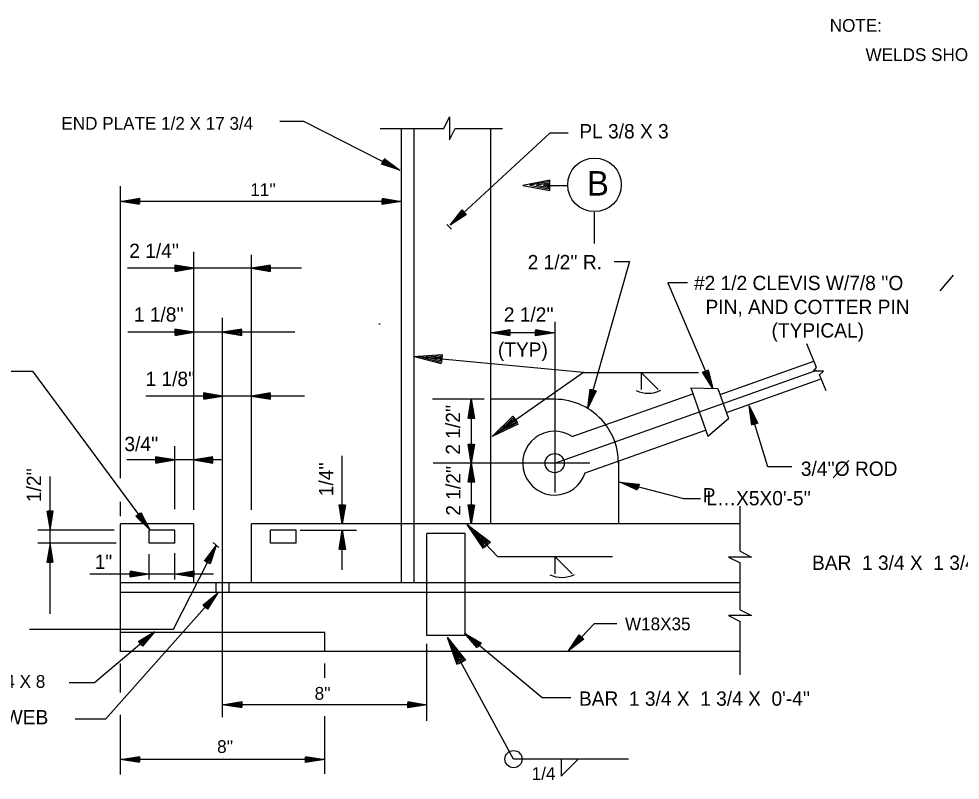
# Model space of a CAD drawing. Extents: x 0 to 13.3, y 0 to 9.3.
# Drawn here: x 2.16 to 5.231, y 1.508 to 3.991 of the extents above; entities that cross this region are included whole.
import ezdxf

# ---------------------------------------------------------------- set-up
doc = ezdxf.new("R2010")
doc.units = 0
for name, color, linetype in [('Level 13', 7, 'Continuous'), ('Level 2', 7, 'Continuous'), ('Level 25', 7, 'Continuous'), ('Level 3', 7, 'Continuous'), ('Level 44', 7, 'Continuous'), ('Level 50', 7, 'Continuous'), ('Level 7', 7, 'Continuous')]:
    doc.layers.add(name, color=color, linetype=linetype)

msp = doc.modelspace()

# ---------------------------------------------------------------- linework, layer by layer
at = {"layer": 'Level 13'}
for points in [[(3.5462, 3.6338), (3.5649, 3.6713), (3.5649, 3.5964), (3.5836, 3.6338)], [(4.5132, 2.2542), (4.5507, 2.2356), (4.4758, 2.2356), (4.5132, 2.2168)], [(4.5132, 2.0631), (4.5507, 2.0444), (4.4758, 2.0444), (4.5132, 2.0257)]]:
    msp.add_lwpolyline(points, dxfattribs=at)
at = {"layer": 'Level 2'}
for p, q in [((3.4081, 2.3437), (3.4081, 3.6338)), ((3.4497, 2.3437), (3.4497, 3.6338)), ((3.6997, 2.3437), (3.6997, 3.6338)), ((3.9082, 3.0024), (3.9082, 2.4464)), ((4.7627, 2.8541), (4.7304, 2.9316)), ((4.4478, 2.7663), (4.7536, 2.8746)), ((3.9082, 2.5419), (4.764, 2.8452)), ((4.7527, 2.8419), (4.7627, 2.8541)), ((4.7848, 2.8419), (4.7527, 2.8419)), ((4.7727, 2.8299), (4.7848, 2.8419)), ((4.7944, 2.7778), (4.7727, 2.8299)), ((4.4687, 2.7074), (4.7745, 2.8157)), ((3.9658, 2.6287), (4.3588, 2.7679)), ((4.3519, 2.7876), (4.4075, 2.6304)), ((4.3519, 2.7876), (4.4409, 2.7859)), ((4.4409, 2.7859), (4.4757, 2.6877)), ((3.9082, 2.7503), (3.6997, 2.7503)), ((4.4075, 2.6304), (4.4757, 2.6877)), ((4.0076, 2.5108), (4.4006, 2.65)), ((4.1166, 2.5494), (4.1166, 2.3437)), ((4.0226, 2.5419), (3.5122, 2.5419)), ((4.1166, 2.5419), (4.1166, 2.5377)), ((4.5132, 2.2542), (4.5132, 2.4014)), ((2.7311, 2.3437), (2.4914, 2.3437)), ((2.4914, 1.9271), (2.4914, 2.3437)), ((2.7311, 2.151), (2.7311, 2.3437)), ((2.9187, 2.151), (2.9187, 2.3437)), ((4.5132, 2.3437), (2.9187, 2.3437)), ((3.4081, 2.151), (3.4081, 2.3437)), ((3.4497, 2.151), (3.4497, 2.3437)), ((2.6685, 2.3229), (2.5852, 2.3229)), ((2.5852, 2.2812), (2.5852, 2.3229)), ((2.6685, 2.2812), (2.6685, 2.3229)), ((2.9812, 2.2812), (2.9812, 2.3229)), ((3.0646, 2.3229), (2.9812, 2.3229)), ((3.0646, 2.2812), (3.0646, 2.3229)), ((3.4914, 1.9791), (3.4914, 2.3125)), ((3.6164, 2.3125), (3.4914, 2.3125)), ((3.6164, 1.9791), (3.6164, 2.3125)), ((2.6685, 2.2812), (2.5852, 2.2812)), ((3.0646, 2.2812), (2.9812, 2.2812)), ((4.5132, 2.0631), (4.5132, 2.2168)), ((4.5132, 2.151), (2.4914, 2.151)), ((2.9187, 2.151), (2.7311, 2.151)), ((2.804, 2.1198), (2.804, 2.151)), ((2.8457, 2.1198), (2.8457, 2.151)), ((4.5132, 2.1198), (2.4914, 2.1198)), ((4.5132, 1.8511), (4.5132, 2.0257)), ((3.1581, 1.9896), (2.4914, 1.9896)), ((3.1581, 1.9271), (3.1581, 1.9896)), ((3.6164, 1.9791), (3.4914, 1.9791)), ((4.5132, 1.9271), (2.4914, 1.9271))]:
    msp.add_line(p, q, dxfattribs=at)
msp.add_circle((3.9081, 2.5419), 0.0313, dxfattribs=at)
for radius, start, end in [(0.2084, 39.3557, 90), (0.2084, 0, 39.3557), (0.1042, 56.3868, 342.6378)]:
    msp.add_arc((3.9081, 2.5419), radius, start, end, dxfattribs=at)
at = {"layer": 'Level 25'}
for p, q in [((4.0026, 2.8378), (3.4471, 2.8901)), ((3.4471, 2.8901), (3.4471, 2.8901)), ((3.4729, 2.8877), (3.4729, 2.8877)), ((4.0026, 2.8378), (4.3777, 2.8378)), ((4.1901, 2.8378), (4.1901, 2.7816)), ((4.1901, 2.8378), (4.246, 2.7819)), ((3.7254, 2.6432), (3.7254, 2.6432)), ((3.7041, 2.6283), (3.7041, 2.6283)), ((3.6232, 2.342), (3.6232, 2.342)), ((3.6409, 2.323), (3.6409, 2.323)), ((3.7213, 2.2371), (4.0964, 2.2371)), ((3.9088, 2.2371), (3.9088, 2.1809)), ((3.9088, 2.2371), (3.9648, 2.1812)), ((3.5587, 1.9735), (3.5587, 1.9735)), ((3.5711, 1.9507), (3.5711, 1.9507)), ((4.1491, 1.5763), (3.774, 1.5763)), ((3.9294, 1.5769), (3.9294, 1.5207)), ((3.9294, 1.5207), (3.9853, 1.5765))]:
    msp.add_line(p, q, dxfattribs=at)
for points in [[(3.5387, 2.8659), (3.4471, 2.8901), (3.5416, 2.8968), (3.5391, 2.8704), (3.4729, 2.8877), (3.5371, 2.8922), (3.5356, 2.8752), (3.4978, 2.8853), (3.5327, 2.8876), (3.532, 2.8806), (3.5237, 2.8829)], [(3.7895, 2.6693), (3.7041, 2.6283), (3.7717, 2.6947), (3.7869, 2.673), (3.7254, 2.6432), (3.7713, 2.6883), (3.7811, 2.6744), (3.7458, 2.6576), (3.7709, 2.6819), (3.7749, 2.6762), (3.7671, 2.6725)], [(3.6758, 2.2631), (3.6232, 2.342), (3.6984, 2.2843), (3.679, 2.2662), (3.6409, 2.323), (3.692, 2.2838), (3.6796, 2.2722), (3.658, 2.3048), (3.6856, 2.2833), (3.6805, 2.2785), (3.6758, 2.2858)], [(3.5896, 1.8839), (3.5587, 1.9735), (3.6169, 1.8987), (3.5936, 1.8861), (3.5711, 1.9507), (3.6106, 1.8999), (3.5956, 1.8918), (3.583, 1.9287), (3.6043, 1.901), (3.5981, 1.8976), (3.5954, 1.9058)]]:
    msp.add_lwpolyline(points, dxfattribs=at)
at = {"layer": 'Level 3'}
for p, q in [((3.3877, 3.5059), (3.3877, 3.5059)), ((3.4031, 3.4981), (3.4031, 3.4981)), ((2.4914, 2.4925), (2.4914, 3.445)), ((3.8922, 3.4481), (3.9505, 3.4481)), ((3.4081, 3.3957), (2.4914, 3.3957)), ((4.038, 3.2589), (4.038, 3.3608)), ((3.5671, 3.3187), (3.5671, 3.3187)), ((3.5799, 3.3304), (3.5799, 3.3304)), ((2.7311, 2.3891), (2.7311, 3.2307)), ((2.9187, 2.3891), (2.9187, 3.221)), ((2.7311, 3.1775), (2.515, 3.1775)), ((2.7137, 3.1775), (2.7137, 3.1775)), ((2.9187, 3.1775), (2.7311, 3.1775)), ((2.7311, 3.1775), (2.7311, 3.1775)), ((3.0826, 3.1775), (2.9187, 3.1775)), ((2.9187, 3.1775), (2.9187, 3.1775)), ((2.936, 3.1775), (2.936, 3.1775)), ((5.1656, 3.1045), (5.2094, 3.1553)), ((2.8249, 1.7128), (2.8249, 3.0163)), ((3.339, 2.9955), (3.3345, 2.9955)), ((2.7311, 2.969), (2.5156, 2.969)), ((2.7137, 2.969), (2.7137, 2.969)), ((2.8249, 2.969), (2.7311, 2.969)), ((2.7311, 2.969), (2.7311, 2.969)), ((3.0602, 2.969), (2.8249, 2.969)), ((2.8249, 2.969), (2.8249, 2.969)), ((2.8422, 2.969), (2.8422, 2.969)), ((3.9082, 2.9671), (3.6997, 2.9671)), ((4.4174, 2.8011), (4.4174, 2.8011)), ((4.4241, 2.7851), (4.4241, 2.7851)), ((2.8249, 2.7606), (2.5738, 2.7606)), ((2.8075, 2.7606), (2.8075, 2.7606)), ((2.9187, 2.7606), (2.8249, 2.7606)), ((2.8249, 2.7606), (2.8249, 2.7606)), ((3.0922, 2.7606), (2.9187, 2.7606)), ((2.9187, 2.7606), (2.9187, 2.7606)), ((2.936, 2.7606), (2.936, 2.7606)), ((3.6783, 2.7503), (3.5101, 2.7503)), ((3.6359, 2.7503), (3.6359, 2.5419)), ((4.0214, 2.7374), (4.0214, 2.7374)), ((4.0167, 2.7207), (4.0167, 2.7207)), ((4.5432, 2.7286), (4.5432, 2.7286)), ((4.5482, 2.712), (4.5482, 2.712)), ((2.6685, 2.3923), (2.6685, 2.5971)), ((2.6685, 2.5522), (2.5122, 2.5522)), ((2.6512, 2.5522), (2.6512, 2.5522)), ((2.7311, 2.5522), (2.6685, 2.5522)), ((2.6685, 2.5522), (2.6685, 2.5522)), ((2.8202, 2.5522), (2.7311, 2.5522)), ((2.7311, 2.5522), (2.7311, 2.5522)), ((2.7484, 2.5522), (2.7484, 2.5522)), ((3.2151, 2.3437), (3.2151, 2.5652)), ((4.8168, 2.4938), (4.8674, 2.5505)), ((3.6359, 2.5419), (3.6359, 2.3437)), ((2.2621, 2.3229), (2.2621, 2.4979)), ((4.1211, 2.4795), (4.1211, 2.4795)), ((4.1379, 2.4751), (4.1379, 2.4751)), ((2.4914, 2.3694), (2.4914, 2.4159)), ((2.2621, 2.3402), (2.2621, 2.3402)), ((2.5768, 2.3388), (2.5768, 2.3388)), ((2.4714, 2.3229), (2.2218, 2.3229)), ((2.2621, 2.2611), (2.2621, 2.3229)), ((2.2621, 2.3229), (2.2621, 2.3229)), ((2.5871, 2.3248), (2.5871, 2.3248)), ((3.2151, 2.1941), (3.2151, 2.3229)), ((2.4778, 2.2812), (2.2218, 2.2812)), ((2.2621, 2.0499), (2.2621, 2.2812)), ((2.2621, 2.2812), (2.2621, 2.2812)), ((2.8036, 2.2733), (2.8036, 2.2733)), ((2.2621, 2.2639), (2.2621, 2.2639)), ((2.5852, 2.1626), (2.5852, 2.2451)), ((2.6685, 2.1626), (2.6685, 2.2483)), ((2.7958, 2.2579), (2.7958, 2.2579)), ((2.5852, 2.18), (2.3912, 2.18)), ((2.6685, 2.18), (2.5852, 2.18)), ((2.7946, 2.18), (2.6685, 2.18)), ((2.4429, 1.7062), (2.809, 2.1184)), ((2.5908, 1.9813), (2.5908, 1.9813)), ((2.604, 1.9924), (2.604, 1.9924)), ((3.6145, 1.9871), (3.6145, 1.9871)), ((3.6278, 1.976), (3.6278, 1.976)), ((3.4914, 1.7016), (3.4914, 1.9529)), ((3.9654, 1.9417), (3.9654, 1.9417)), ((3.9536, 1.9291), (3.9536, 1.9291)), ((2.4914, 1.7936), (2.4914, 1.8878)), ((3.1581, 1.8418), (3.1581, 1.8878)), ((3.4914, 1.7535), (2.8249, 1.7535)), ((2.4914, 1.5259), (2.4914, 1.7213)), ((2.4429, 1.7062), (2.3437, 1.7062)), ((3.1581, 1.5284), (3.1581, 1.7164)), ((3.1581, 1.5751), (2.4914, 1.5751))]:
    msp.add_line(p, q, dxfattribs=at)
for points in [[(3.0117, 3.6578), (3.0882, 3.6578), (3.4031, 3.4981)], [(3.952, 3.6184), (3.8929, 3.6184), (3.5671, 3.3187)], [(3.3522, 3.5355), (3.4031, 3.4981), (3.3429, 3.517), (3.3508, 3.5328), (3.3877, 3.5059), (3.3467, 3.5188), (3.3519, 3.5289), (3.3728, 3.5134), (3.3506, 3.5206), (3.3527, 3.5247), (3.3573, 3.5213)], [(3.8922, 3.4604), (3.8922, 3.4648), (3.8047, 3.4481), (3.8922, 3.4318), (3.8922, 3.4604), (3.827, 3.4484), (3.888, 3.4368), (3.888, 3.4556), (3.849, 3.4484), (3.8839, 3.4419), (3.8839, 3.4506), (3.8714, 3.4484), (3.8797, 3.4468)], [(3.62, 3.3533), (3.5671, 3.3187), (3.606, 3.3685), (3.618, 3.3555), (3.5799, 3.3304), (3.6063, 3.3642), (3.614, 3.3559), (3.5921, 3.3417), (3.6066, 3.3599), (3.6097, 3.3565), (3.6049, 3.3534)], [(4.1024, 3.1993), (4.1521, 3.1993), (4.0167, 2.7207)], [(2.6687, 3.1671), (2.7311, 3.1775), (2.6687, 3.1878), (2.6687, 3.1701), (2.7137, 3.1775), (2.6714, 3.1845), (2.6714, 3.1731), (2.6971, 3.1775), (2.6741, 3.1811), (2.6741, 3.1765), (2.6797, 3.1775)], [(2.981, 3.1878), (2.9187, 3.1775), (2.981, 3.1671), (2.981, 3.1848), (2.936, 3.1775), (2.9784, 3.1705), (2.9784, 3.1818), (2.9527, 3.1775), (2.9757, 3.1738), (2.9757, 3.1785), (2.97, 3.1775)], [(4.3411, 3.1297), (4.2774, 3.1297), (4.4241, 2.7851)], [(2.6687, 2.9587), (2.7311, 2.969), (2.6687, 2.9794), (2.6687, 2.9617), (2.7137, 2.969), (2.6714, 2.976), (2.6714, 2.9647), (2.6971, 2.969), (2.6741, 2.9727), (2.6741, 2.968), (2.6797, 2.969)], [(2.8872, 2.9794), (2.8249, 2.969), (2.8872, 2.9587), (2.8872, 2.9764), (2.8422, 2.969), (2.8846, 2.962), (2.8846, 2.9734), (2.8589, 2.969), (2.8819, 2.9654), (2.8819, 2.97), (2.8762, 2.969)], [(1.9936, 2.8419), (2.2049, 2.8419), (2.5871, 2.3248)], [(4.4092, 2.8465), (4.4241, 2.7851), (4.3902, 2.8384), (4.4065, 2.8453), (4.4174, 2.8011), (4.3943, 2.8373), (4.4048, 2.8417), (4.4108, 2.8164), (4.3984, 2.8361), (4.4027, 2.8379), (4.404, 2.8323)], [(2.7625, 2.7503), (2.8249, 2.7606), (2.7625, 2.7709), (2.7625, 2.7533), (2.8075, 2.7606), (2.7652, 2.7676), (2.7652, 2.7563), (2.7909, 2.7606), (2.7678, 2.7643), (2.7678, 2.7596), (2.7735, 2.7606)], [(2.981, 2.7709), (2.9187, 2.7606), (2.981, 2.7503), (2.981, 2.7679), (2.936, 2.7606), (2.9784, 2.7536), (2.9784, 2.7649), (2.9527, 2.7606), (2.9757, 2.7569), (2.9757, 2.7616), (2.97, 2.7606)], [(4.0436, 2.7779), (4.0167, 2.7207), (4.0237, 2.7835), (4.0407, 2.7787), (4.0214, 2.7374), (4.0262, 2.7801), (4.0371, 2.777), (4.026, 2.7535), (4.0287, 2.7766), (4.0332, 2.7753), (4.0307, 2.7701)], [(4.6816, 2.5294), (4.6041, 2.5294), (4.5432, 2.7286)], [(4.5515, 2.6659), (4.5432, 2.7286), (4.5713, 2.672), (4.5544, 2.6668), (4.5482, 2.712), (4.5673, 2.6736), (4.5565, 2.6703), (4.5531, 2.6961), (4.5633, 2.6751), (4.5589, 2.6738), (4.5582, 2.6795)], [(2.6062, 2.5418), (2.6685, 2.5522), (2.6062, 2.5625), (2.6062, 2.5448), (2.6512, 2.5522), (2.6088, 2.5592), (2.6088, 2.5478), (2.6345, 2.5522), (2.6115, 2.5558), (2.6115, 2.5512), (2.6172, 2.5522)], [(2.7934, 2.5625), (2.7311, 2.5522), (2.7934, 2.5418), (2.7934, 2.5595), (2.7484, 2.5522), (2.7908, 2.5452), (2.7908, 2.5565), (2.7651, 2.5522), (2.7881, 2.5485), (2.7881, 2.5532), (2.7824, 2.5522)], [(4.3842, 2.4254), (4.3301, 2.4254), (4.1211, 2.4795)], [(4.1789, 2.4538), (4.1211, 2.4795), (4.184, 2.4738), (4.1796, 2.4567), (4.1379, 2.4751), (4.1806, 2.4713), (4.1778, 2.4603), (4.154, 2.4709), (4.1772, 2.4687), (4.176, 2.4642), (4.1708, 2.4666)], [(2.2518, 2.3853), (2.2621, 2.3229), (2.2724, 2.3853), (2.2548, 2.3853), (2.2621, 2.3402), (2.2691, 2.3826), (2.2578, 2.3826), (2.2621, 2.3569), (2.2658, 2.3799), (2.2611, 2.3799), (2.2621, 2.3742)], [(2.5584, 2.3811), (2.5871, 2.3248), (2.5418, 2.3688), (2.556, 2.3793), (2.5768, 2.3388), (2.546, 2.3687), (2.5551, 2.3754), (2.5669, 2.3522), (2.5503, 2.3685), (2.554, 2.3713), (2.5566, 2.3661)], [(2.1949, 2.0008), (2.6649, 2.0008), (2.8036, 2.2733)], [(2.2724, 2.2188), (2.2621, 2.2812), (2.2518, 2.2188), (2.2694, 2.2188), (2.2621, 2.2639), (2.2551, 2.2215), (2.2664, 2.2215), (2.2621, 2.2472), (2.2584, 2.2242), (2.2631, 2.2242), (2.2621, 2.2298)], [(2.7662, 2.2225), (2.8036, 2.2733), (2.7846, 2.2131), (2.7688, 2.2211), (2.7958, 2.2579), (2.7828, 2.217), (2.7727, 2.2221), (2.7882, 2.243), (2.7811, 2.2209), (2.7769, 2.223), (2.7804, 2.2276)], [(4.1114, 2.0179), (4.0366, 2.0179), (3.9536, 1.9291)], [(2.3245, 1.8268), (2.4066, 1.8268), (2.604, 1.9924)], [(2.5496, 1.9603), (2.604, 1.9924), (2.5629, 1.9444), (2.5516, 1.958), (2.5908, 1.9813), (2.5628, 1.9487), (2.5555, 1.9574), (2.578, 1.9706), (2.5627, 1.953), (2.5597, 1.9566), (2.5647, 1.9594)], [(3.9614, 1.7761), (3.867, 1.7761), (3.6145, 1.9871)], [(3.6557, 1.9392), (3.6145, 1.9871), (3.669, 1.955), (3.6576, 1.9415), (3.6278, 1.976), (3.6648, 1.9542), (3.6575, 1.9455), (3.6406, 1.9653), (3.6606, 1.9533), (3.6576, 1.9498), (3.6539, 1.9542)], [(4.0037, 1.9676), (3.9536, 1.9291), (3.9886, 1.9817), (4.0015, 1.9696), (3.9654, 1.9417), (3.9892, 1.9774), (3.9975, 1.9697), (3.9768, 1.9539), (3.9898, 1.9732), (3.9933, 1.97), (3.9886, 1.9666)]]:
    msp.add_lwpolyline(points, dxfattribs=at)
msp.add_circle((4.0381, 3.4498), 0.0875, dxfattribs=at)
at = {"layer": 'Level 50'}
for p, q in [((3.3383, 3.6338), (3.5462, 3.6338)), ((3.5836, 3.6338), (3.7378, 3.6338)), ((2.4914, 3.3957), (2.4914, 3.3957)), ((2.5087, 3.3957), (2.5087, 3.3957)), ((3.3907, 3.3957), (3.3907, 3.3957)), ((3.4081, 3.3957), (3.4081, 3.3957)), ((3.5562, 3.3208), (3.5715, 3.3055)), ((3.6997, 2.9671), (3.6997, 2.9671)), ((3.7171, 2.9671), (3.7171, 2.9671)), ((3.8908, 2.9671), (3.8908, 2.9671)), ((3.9082, 2.9671), (3.9082, 2.9671)), ((4.0026, 2.8378), (3.7041, 2.6283)), ((3.6359, 2.7503), (3.6359, 2.7503)), ((3.6359, 2.733), (3.6359, 2.733)), ((3.6359, 2.5592), (3.6359, 2.5592)), ((3.6359, 2.5419), (3.6359, 2.5419)), ((3.6359, 2.5419), (3.6359, 2.5419)), ((3.6359, 2.5246), (3.6359, 2.5246)), ((3.2151, 2.3611), (3.2151, 2.3611)), ((3.2151, 2.3437), (3.2151, 2.3437)), ((3.7213, 2.2371), (3.6232, 2.342)), ((3.6359, 2.3611), (3.6359, 2.3611)), ((3.6359, 2.3437), (3.6359, 2.3437)), ((3.0775, 2.3229), (3.2613, 2.3229)), ((3.2151, 2.3229), (3.2151, 2.3229)), ((3.2151, 2.3056), (3.2151, 2.3056)), ((2.7941, 2.2833), (2.8122, 2.2665)), ((2.5678, 2.18), (2.5678, 2.18)), ((2.5852, 2.18), (2.5852, 2.18)), ((2.6685, 2.18), (2.6685, 2.18)), ((2.6859, 2.18), (2.6859, 2.18)), ((2.7974, 2.1055), (2.7974, 2.1055)), ((2.809, 2.1184), (2.809, 2.1184)), ((3.774, 1.5763), (3.5587, 1.9735)), ((2.8249, 1.7535), (2.8249, 1.7535)), ((2.8422, 1.7535), (2.8422, 1.7535)), ((3.4741, 1.7535), (3.4741, 1.7535)), ((3.4914, 1.7535), (3.4914, 1.7535)), ((2.4914, 1.5751), (2.4914, 1.5751)), ((2.5087, 1.5751), (2.5087, 1.5751)), ((3.1407, 1.5751), (3.1407, 1.5751)), ((3.1581, 1.5751), (3.1581, 1.5751))]:
    msp.add_line(p, q, dxfattribs=at)
for points in [[(2.5537, 3.3854), (2.4914, 3.3957), (2.5537, 3.406), (2.5537, 3.3884), (2.5087, 3.3957), (2.5511, 3.4027), (2.5511, 3.3914), (2.5254, 3.3957), (2.5484, 3.3994), (2.5484, 3.3947), (2.5427, 3.3957)], [(3.3457, 3.406), (3.4081, 3.3957), (3.3457, 3.3854), (3.3457, 3.403), (3.3907, 3.3957), (3.3484, 3.3887), (3.3484, 3.4), (3.3741, 3.3957), (3.3511, 3.392), (3.3511, 3.3967), (3.3567, 3.3957)], [(3.7621, 2.9567), (3.6997, 2.9671), (3.7621, 2.9774), (3.7621, 2.9597), (3.7171, 2.9671), (3.7594, 2.9741), (3.7594, 2.9627), (3.7337, 2.9671), (3.7567, 2.9707), (3.7567, 2.9661), (3.7511, 2.9671)], [(3.8458, 2.9774), (3.9082, 2.9671), (3.8458, 2.9567), (3.8458, 2.9744), (3.8908, 2.9671), (3.8485, 2.9601), (3.8485, 2.9714), (3.8742, 2.9671), (3.8512, 2.9634), (3.8512, 2.9681), (3.8568, 2.9671)], [(3.6256, 2.688), (3.6359, 2.7503), (3.6462, 2.688), (3.6286, 2.688), (3.6359, 2.733), (3.6429, 2.6907), (3.6316, 2.6907), (3.6359, 2.7163), (3.6396, 2.6933), (3.6349, 2.6933), (3.6359, 2.699)], [(3.6462, 2.6042), (3.6359, 2.5419), (3.6256, 2.6042), (3.6432, 2.6042), (3.6359, 2.5592), (3.6289, 2.6016), (3.6402, 2.6016), (3.6359, 2.5759), (3.6322, 2.5989), (3.6369, 2.5989), (3.6359, 2.5932)], [(3.6256, 2.4796), (3.6359, 2.5419), (3.6462, 2.4796), (3.6286, 2.4796), (3.6359, 2.5246), (3.6429, 2.4822), (3.6316, 2.4822), (3.6359, 2.5079), (3.6396, 2.4849), (3.6349, 2.4849), (3.6359, 2.4906)], [(3.2254, 2.4061), (3.2151, 2.3437), (3.2047, 2.4061), (3.2224, 2.4061), (3.2151, 2.3611), (3.2081, 2.4034), (3.2194, 2.4034), (3.2151, 2.3777), (3.2114, 2.4007), (3.2161, 2.4007), (3.2151, 2.3951)], [(3.6462, 2.4061), (3.6359, 2.3437), (3.6256, 2.4061), (3.6432, 2.4061), (3.6359, 2.3611), (3.6289, 2.4034), (3.6402, 2.4034), (3.6359, 2.3777), (3.6322, 2.4007), (3.6369, 2.4007), (3.6359, 2.3951)], [(3.2047, 2.2606), (3.2151, 2.3229), (3.2254, 2.2606), (3.2077, 2.2606), (3.2151, 2.3056), (3.2221, 2.2632), (3.2107, 2.2632), (3.2151, 2.2889), (3.2187, 2.2659), (3.2141, 2.2659), (3.2151, 2.2716)], [(2.5228, 2.1903), (2.5852, 2.18), (2.5228, 2.1697), (2.5228, 2.1873), (2.5678, 2.18), (2.5255, 2.173), (2.5255, 2.1843), (2.5512, 2.18), (2.5282, 2.1763), (2.5282, 2.181), (2.5338, 2.18)], [(2.7309, 2.1697), (2.6685, 2.18), (2.7309, 2.1903), (2.7309, 2.1727), (2.6859, 2.18), (2.7282, 2.187), (2.7282, 2.1757), (2.7025, 2.18), (2.7255, 2.1837), (2.7255, 2.179), (2.7199, 2.18)], [(2.7598, 2.0787), (2.809, 2.1184), (2.7753, 2.065), (2.7621, 2.0767), (2.7974, 2.1055), (2.7746, 2.0692), (2.7661, 2.0767), (2.7864, 2.093), (2.7739, 2.0734), (2.7704, 2.0765), (2.7749, 2.0801)], [(2.8872, 1.7432), (2.8249, 1.7535), (2.8872, 1.7639), (2.8872, 1.7462), (2.8422, 1.7535), (2.8845, 1.7605), (2.8845, 1.7492), (2.8589, 1.7535), (2.8819, 1.7572), (2.8819, 1.7525), (2.8762, 1.7535)], [(3.4291, 1.7639), (3.4914, 1.7535), (3.4291, 1.7432), (3.4291, 1.7609), (3.4741, 1.7535), (3.4317, 1.7465), (3.4317, 1.7579), (3.4574, 1.7535), (3.4344, 1.7499), (3.4344, 1.7545), (3.4401, 1.7535)], [(2.5537, 1.5648), (2.4914, 1.5751), (2.5537, 1.5854), (2.5537, 1.5678), (2.5087, 1.5751), (2.5511, 1.5821), (2.5511, 1.5708), (2.5254, 1.5751), (2.5484, 1.5788), (2.5484, 1.5741), (2.5427, 1.5751)], [(3.0957, 1.5854), (3.1581, 1.5751), (3.0957, 1.5648), (3.0957, 1.5824), (3.1407, 1.5751), (3.0984, 1.5681), (3.0984, 1.5794), (3.1241, 1.5751), (3.1011, 1.5714), (3.1011, 1.5761), (3.1067, 1.5751)]]:
    msp.add_lwpolyline(points, dxfattribs=at)
for centre in [(4.2128, 2.8642), (3.9316, 2.2635)]:
    msp.add_arc(centre, 0.0943, 245.5194, 296.0807, dxfattribs=at)
at = {"layer": 'Level 7'}
msp.add_circle((3.774, 1.5763), 0.0281, dxfattribs=at)

# ---------------------------------------------------------------- texts
at = {"layer": 'Level 3'}
for s, height, p in [('PL 3/8 X 3', 0.04669, (3.9887, 3.6013)), ('B', 0.08, (4.0138, 3.4148)), ("2 1/4''", 0.04669, (2.5201, 3.2111)), ("2 1/2'' R.", 0.04667, (3.8202, 3.1743)), ("#2 1/2 CLEVIS W/7/8 ''O", 0.046674, (4.3627, 3.1063)), ('PIN, AND COTTER PIN', 0.046674, (4.4003, 3.0283)), ("1 1/8''", 0.04669, (2.5353, 3.0035)), ("2 1/2''", 0.04667, (3.7423, 3.0034)), ('(TYPICAL)', 0.04667, (4.6157, 2.9517)), ('(TYP)', 0.04667, (3.723, 2.8888)), ("1 1/8''", 0.04669, (2.5731, 2.7934)), ("3/4''", 0.04669, (2.5044, 2.5811)), ("3/4''O ROD", 0.04667, (4.7114, 2.5004)), ('P', 0.0467, (4.3913, 2.4136)), ("L…X5X0'-5''", 0.046677, (4.403, 2.4043)), ('1" ', 0.04669, (2.4075, 2.1965)), ("BAR  1 3/4 X  1 3/4 X  0'-4''", 0.046688, (4.7479, 2.1936)), ("BAR  1 3/4 X  1 3/4 X  0'-4''", 0.046688, (3.9874, 1.7505)), ("13/16'' O HOLE IN WEB", 0.04669, (1.5834, 1.6899))]:
    msp.add_text(s, height=height, dxfattribs=at).set_placement(p)
for s, height, p in [("2 1/2''", 0.04667, (3.5997, 2.5696)), ("1/2''", 0.04669, (2.2325, 2.4149)), ("1/4''", 0.04669, (3.1859, 2.434)), ("2 1/2''", 0.04667, (3.6006, 2.3706))]:
    msp.add_text(s, height=height, rotation=90, dxfattribs=at).set_placement(p)
at = {"layer": 'Level 44'}
for s, height, p in [('NOTE:', 0.0417, (4.8057, 3.949)), ('WELDS SHOWN ARE TYPICAL FOR SIMILAR JOINTS.', 0.041698, (4.9225, 3.8537))]:
    msp.add_text(s, height=height, dxfattribs=at).set_placement(p)
at = {"layer": 'Level 50'}
for s, height, p in [('END PLATE 1/2 X 17 3/4', 0.041698, (2.2987, 3.6296)), ("11''", 0.0417, (2.9151, 3.4132)), ('W18X35', 0.0417, (4.1376, 1.9966)), ('PL 3/4 X 8', 0.0417, (1.9858, 1.8089)), ("8''", 0.04167, (3.1251, 1.7701)), ("8''", 0.04167, (2.8069, 1.5965)), ('1/4', 0.0417, (3.8331, 1.5083))]:
    msp.add_text(s, height=height, dxfattribs=at).set_placement(p)

doc.saveas('drawing.dxf')
